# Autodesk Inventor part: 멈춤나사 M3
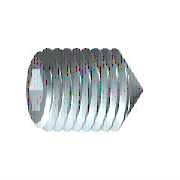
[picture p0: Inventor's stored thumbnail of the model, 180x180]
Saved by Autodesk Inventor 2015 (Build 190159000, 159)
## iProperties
IsCustomPart: 1
Created: 2012-02
Part Number: 멈춤나사 M3
Material: 강철, 연강
Description: 6각 소켓 머리 없는 멈춤 나사
Document SubType Name: Modeling
Standard: KS B 1028
Designer: mduedu
Standards Organization: KS
Language: ko-KR
Size Designation: 원추점 M3x6
Categories: <MemberInstance><Categories><Category DisplayName="조임쇠" InternalName="e4da775c-781d-43d5-af7c-5136215cf5a6" Mnemonic="FSTN"><Category DisplayName="볼트" InternalN
Density: 1 g/cm^3
Appearance: 노란색
Author: mduedu
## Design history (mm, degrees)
sketch "스케치1"
  geometry: L1 (0, 0)-(3.5, 0); L2 (6, 0.866)-(6, 1.5); L3 (6, 1.5)-(0, 1.5); L4 (6, 0.866)-(4, 0.866); L5 (4, 0.866)-(3.5, 0); L6 (0, -0.3)-(0, 1.8) reference; L7 (0, 1.5)-(0, 0)
  constraints: 13 end point, 3 parallel, 1 collinear, 1 perpendicular, 1 point on line
  dimensions: "d0" = 2 distance of L2.start L4.end (= INTI); "d1" = 60 deg angle of L5 L1; "d2" = 3 diameter of L3 L1 (= NND); "d3" = 1.73205 diameter of L4 L1 (= 1.1547 x SW); "d5" = 6 distance from line of L2 L3.end (= NLG)
revolve "본체" sketch "스케치1" stored, may be unused: angle "d6" = 90 deg
sketch "스케치2"
  geometry: L1 (-0.433, 0.75)-(0.433, 0.75); L2 (0.433, 0.75)-(0.866, 0); L3 (0.866, 0)-(0.433, -0.75); L4 (0.433, -0.75)-(-0.433, -0.75); L5 (-0.433, -0.75)-(-0.866, 0); L6 (-0.866, 0)-(-0.433, 0.75); 3 further points
  constraints: 12 end point, 1 coincident, 1 horizontal, 13 other
extrude "슬롯" join sketch "스케치2" taper "d7" = 0 deg; stored distance "d21" = 10
workaxis "Work Axis1"
workplane "Work Plane1"
body "Solid1"
feature "스레드" dims "d12" = 6 (= NLG), "d13" = 0
chamfer "모따기1" distance "d8" = 1.35 (computed from NND, SPD, FAWI); stored, may be unused: angle "d9" = 45 deg (= FAWI), second distance "d34" = 1.35 (computed from NND, SPD, FAWI)
chamfer "모따기2" distance "d10" = 0.30673 (= -0.5 x GD1 + 0.5 x NND); stored, may be unused: angle "d11" = 45 deg (= FAWI), second distance "d35" = 0.30673 (= -0.5 x GD1 + 0.5 x NND)
other parameters: "NND" = 3 [user parameter; used in 5 equation terms], "NLG" = 6 [user parameter; used in 2 equation terms], "INTI" = 2 [user parameter; used in 1 equation term], "FAWI" = 45 deg [user parameter; used in 4 equation terms], "SW" = 1.5 [user parameter; used in 2 equation terms], "GD1" = 2.38655 (= THREADDIA - 1.2269 x PTC) [user parameter; used in 2 equation terms], "d4" = 0, "FAWI1" = 45 deg [user parameter], "SPD" = 0.3 [user parameter; used in 2 equation terms], "d36" = 0, "d37" = 0, "GUL" = 0.30673 (= 0.61345 x PTC) [user parameter], "TOA" = 30 deg [user parameter], "THREADDIA" = 3 [user parameter; used in 1 equation term], "PTC" = 0.5 [user parameter; used in 4 equation terms], "GAL" = 0.30673 (= 0.61345 x PTC) [user parameter], "E0" = 1.7325 (= 1.155 x SW) [user parameter]
